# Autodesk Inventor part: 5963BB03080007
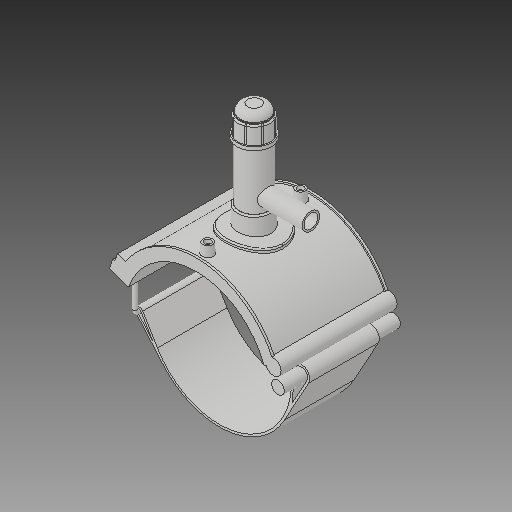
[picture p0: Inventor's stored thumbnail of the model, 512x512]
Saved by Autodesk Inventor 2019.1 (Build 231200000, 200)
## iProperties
Created: 2017-07
Part Number: 5963BB03080007
Material: Generic
Description: PLASSON TAPPING SADDLE 8''IPS x 1 3/4''IPS
Document SubType Name: Modeling
Designer: KIM
Mass: 1712.7 g
Surface Area: 2671.49 cm^2
Volume: 1712.7 cm^3
Density: 1 g/cm^3
Appearance: Default
Author: KIM
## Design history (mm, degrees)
derived "5963B.ipt"
feature "Solid1::5963B.ipt"
feature "Solid2::5963B.ipt"
feature "Solid4::5963B.ipt"
feature "Solid5::5963B.ipt"
tag "TaggingFeature1" dims "d0" = 218.7
body "Solid1"
body "Solid2"
other parameters: "d2" = 269.748, "d3" = 54.675, "d4" = 176.022, "d5" = 0, "d6" = 0.1, "d8" = 0, "d19" = 6, "d20" = 6, "d21" = 105.6132, "d23" = 0, "d24" = 52.8066, "d26" = 0, "d29" = 3, "d30" = 72.9, "d31" = 6, "d32" = 0, "d33" = 0, "d34" = 0.6, "d40" = 129.64536, "d41" = 87.48, "d43" = 0, "d45" = 0, "d47" = 230.2722, "d70" = 15, "d72" = 0, "d73" = 6, "d75" = 5, "d76" = 0, "d77" = 10.935, "d78" = 139.35, "d79" = 15, "d80" = 70.4088, "d82" = 5 deg, "d84" = 4, "d85" = 14, "d86" = 0, "d87" = 3, "d88" = 0, "d89" = 1, "d90" = 1, "d91" = 140.8176, "d92" = 0, "d93" = 0.5, "d94" = 115.10526, "d96" = 254.30436, "d97" = 3.52044, "d98" = 0, "d102" = 2.187, "d120" = 140 deg, "d121" = 24.228, "d122" = 20 deg, "d123" = 498.636, "d124" = 149.5908, "d126" = 0, "d143" = 225.261, "d145" = 23.55231, "d149" = 3.2805, "d150" = 25.90754, "d153" = 176.022, "d154" = 0, "d156" = 124.659, "d157" = 160 deg, "d159" = 6.1236, "d161" = 3.2805, "d162" = 105.6132, "d163" = 0, "d164" = 109.35, "d167" = 21.87, "d168" = 121.61854, "d170" = 3.2805, "d172" = 0, "d173" = 1, "d175" = 109.35, "d176" = 20 deg, "d177" = 15.309, "d178" = 30.618, "d180" = 0, "d183" = 12.2472, "d184" = 12.2472, "d185" = 57.20715, "d186" = 57.20715, "d187" = 124.659, "d188" = 9.1854, "d189" = 15.309, "d190" = 0, "d191" = 186.9885, "d193" = 6.1236, "d194" = 6.16077, "d195" = 90 deg, "d197" = 0, "d199" = 0, "d200" = 15.309, "d202" = 0, "d203" = 177.038, "d204" = 49.8636, "d205" = 36.7416, "d206" = 44.6148, "d207" = 132.7785, "d208" = 138.08964, "d209" = 164.64534, "d210" = 45.13968, "d211" = 52.488, "d212" = 41.9904, "d213" = 46.5516, "d216" = 0, "d217" = 21.87, "d218" = 10.935, "d219" = 2.187, "d222" = 218.7, "d224" = 0, "d230" = 2.187, "d233" = 6, "d236" = 89.916, "d237" = 52.8066, "d238" = 6.02433, "d240" = 52.8066, "d241" = 52.8066, "d242" = 52.8066, "d243" = 6, "d244" = 52.8066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
